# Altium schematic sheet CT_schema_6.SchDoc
size 287 x 160 mm
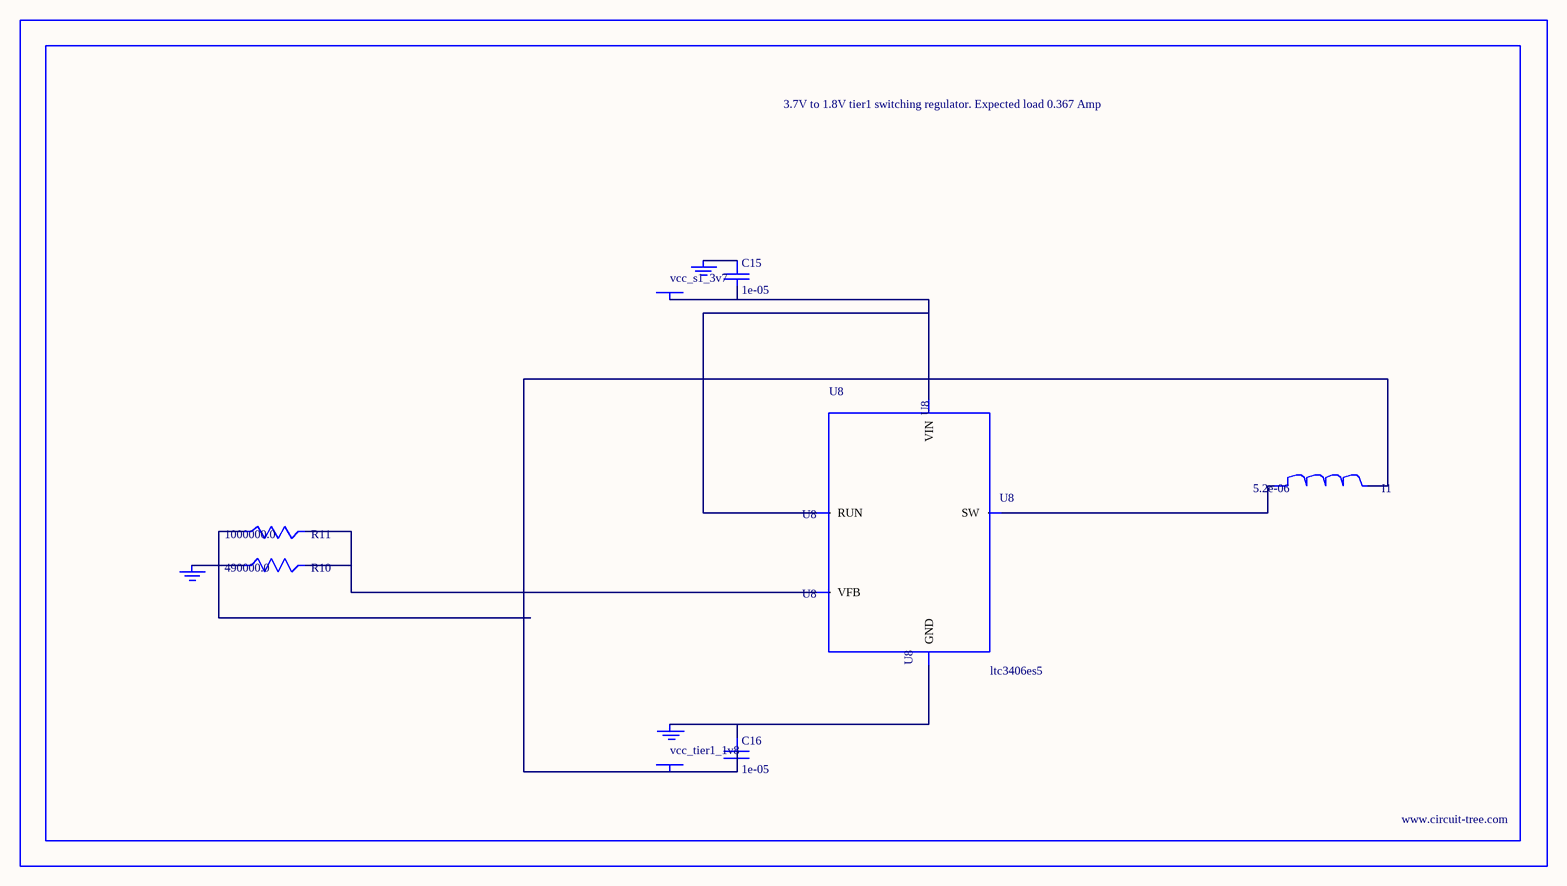
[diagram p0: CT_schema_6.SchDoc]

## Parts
BORDER5  (no value)
C15  1e-05  [C0805]
C16  1e-05  [C0805]
GND_INSTANCE_5_0  (no value)
GND_INSTANCE_5_1  (no value)
GND_INSTANCE_5_2  (no value)
I1  5.2e-06  [DR1040]
POWER_INSTANCE_5_0  vcc_tier1_1v8
POWER_INSTANCE_5_1  vcc_s1_3v7
R10  490000.0  [R0603]
R11  1000000.0  [R0603]
U8  ltc3406es5  [TSOT-23-5]

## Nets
NetC15_1: C15.1 GND_INSTANCE_5_1.0(GND)
NetC15_2: C15.2 POWER_INSTANCE_5_1.0(PWR) U8.1(RUN) U8.4(VIN)
NetC16_1: C16.1 GND_INSTANCE_5_0.0(GND) U8.2(GND)
NetC16_2: C16.2 I1.2 POWER_INSTANCE_5_0.0(PWR) R11.1
NetGND_INSTANCE_5_2_0: GND_INSTANCE_5_2.0(GND) R10.1
NetI1_1: I1.1 U8.3(SW)
NetR10_2: R10.2 R11.2 U8.5(VFB)

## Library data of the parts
BORDER5 = BORDER_PAGE5
C15 C16 = C0805C106K8RACTU
GND_INSTANCE_5_0-GND_INSTANCE_5_2 = GND
I1 = DR1040-5R2-R
POWER_INSTANCE_5_0 POWER_INSTANCE_5_1 = PWR
R10 = R10
R11 = RC0603JR-071ML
